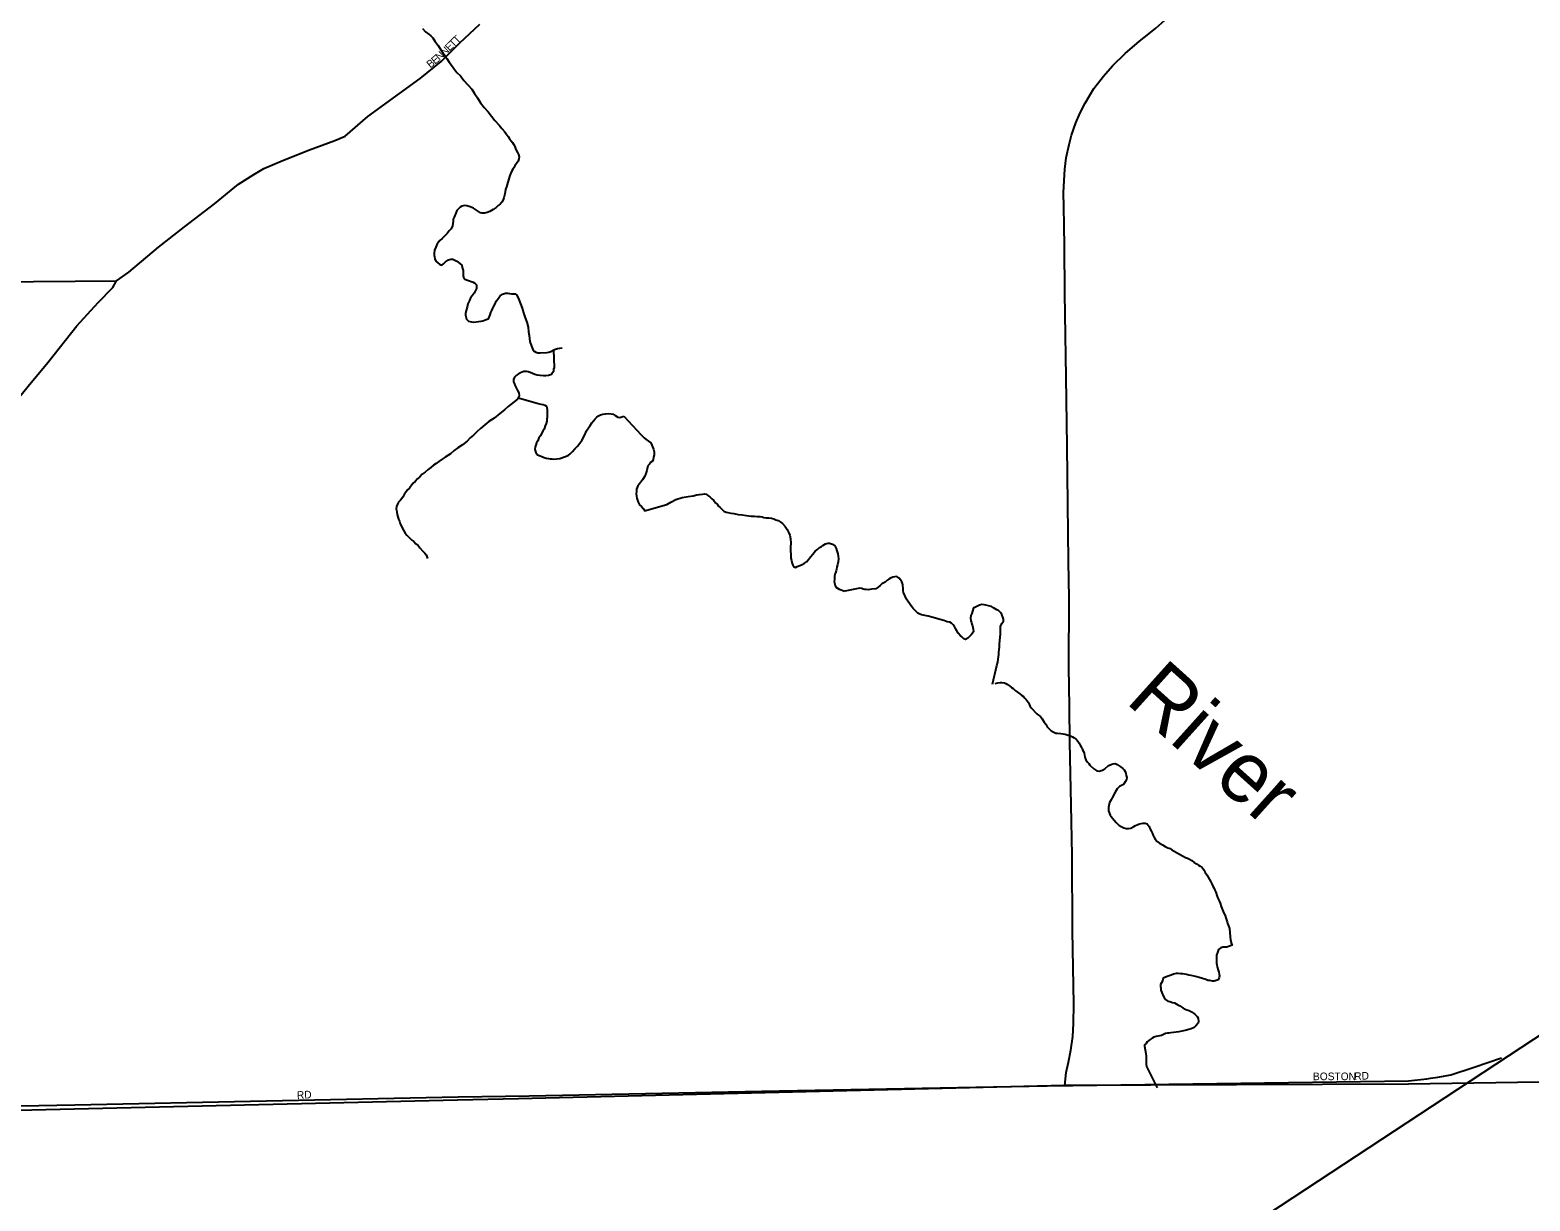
# Model space of a CAD drawing. Extents: x -561 to 1170, y 0 to 846.
# Drawn here: x 187.7 to 214.3, y 67.44 to 88.19 of the extents above; entities that cross this region are included whole.
import ezdxf

# ---------------------------------------------------------------- set-up
doc = ezdxf.new("R2010")
doc.units = 0
for name, color, linetype in [('GM_X_City_Street', 7, 'Continuous'), ('GM_X_City_Street_Text', 7, 'Continuous'), ('GM_X_County', 7, 'Continuous'), ('GM_X_Major_River', 7, 'Continuous'), ('GM_X_Major_River_Text', 7, 'Continuous'), ('GM_X_State_Route', 7, 'Continuous'), ('SH_Text', 7, 'Continuous')]:
    doc.layers.add(name, color=color, linetype=linetype)

msp = doc.modelspace()

# ---------------------------------------------------------------- linework, layer by layer
at = {"layer": 'GM_X_City_Street'}
for points in [[(189.24, 83.747), (189.454, 83.9), (189.985, 84.344), (190.441, 84.705), (190.978, 85.111), (191.401, 85.462), (191.675, 85.632), (191.853, 85.737), (192.202, 85.886), (192.66, 86.069), (193.107, 86.236), (193.29, 86.313), (193.692, 86.664), (194.255, 87.07), (194.62, 87.333), (194.996, 87.634), (195.322, 87.962), (195.681, 88.296)], [(175.794, 83.199), (176.257, 83.284), (177.373, 83.527), (177.605, 83.546), (178.015, 83.593), (178.895, 83.683), (180.439, 83.708), (187.031, 83.731), (189.24, 83.747)], [(179.069, 71.922), (182.409, 75.408), (183.067, 76.215), (184.296, 77.743), (185.113, 78.742), (186.498, 80.439), (187.673, 81.88), (188.021, 82.3), (188.534, 82.949), (188.914, 83.364), (189.176, 83.632), (189.24, 83.747)], [(212.536, 69.612), (212.664, 69.63), (212.897, 69.673), (213.307, 69.809), (213.796, 69.975)], [(178.152, 68.926), (179.747, 68.951), (184.584, 69.065), (186.264, 69.099), (188.502, 69.143), (195.296, 69.284), (196.553, 69.304), (200.677, 69.386), (206.054, 69.485), (206.196, 69.487)], [(206.196, 69.487), (212.144, 69.57), (212.469, 69.603), (212.536, 69.612)]]:
    msp.add_lwpolyline(points, dxfattribs=at)
at = {"layer": 'GM_X_County'}
msp.add_lwpolyline([(282.884, 70.725), (267.704, 70.572), (266.613, 70.549), (250.769, 70.185), (250.464, 70.18), (249.038, 70.146), (242.784, 69.997), (238.571, 69.924), (225.238, 69.779), (224.579, 69.768), (224.275, 69.753), (224.168, 69.735), (224.098, 69.694), (218.724, 69.61), (212.144, 69.507), (206.054, 69.485), (200.736, 69.352), (196.366, 69.25), (195.286, 69.225), (186.974, 69.032)], dxfattribs=at)
at = {"layer": 'GM_X_Major_River'}
for points in [[(194.665, 88.219), (194.714, 88.16), (194.779, 88.117), (194.812, 88.091), (194.845, 88.053), (194.884, 87.994), (194.939, 87.919), (194.989, 87.844), (195.044, 87.763), (195.093, 87.688), (195.138, 87.623), (195.176, 87.57), (195.22, 87.511), (195.27, 87.441), (195.335, 87.382), (195.396, 87.301), (195.467, 87.221), (195.539, 87.146), (195.588, 87.071), (195.638, 86.99), (195.693, 86.904), (195.759, 86.818), (195.825, 86.743), (195.886, 86.668), (195.946, 86.593), (196.023, 86.507), (196.072, 86.448), (196.116, 86.395), (196.149, 86.352), (196.183, 86.309), (196.205, 86.266), (196.238, 86.228), (196.26, 86.201), (196.276, 86.169), (196.298, 86.132), (196.321, 86.078), (196.348, 86.024), (196.365, 85.986), (196.377, 85.948), (196.372, 85.91), (196.361, 85.872), (196.329, 85.829), (196.298, 85.785), (196.282, 85.752), (196.266, 85.725), (196.245, 85.697), (196.224, 85.648), (196.208, 85.6), (196.151, 85.415), (196.135, 85.366), (196.126, 85.29), (196.105, 85.219), (196.094, 85.186), (196.068, 85.143), (196.041, 85.11), (196.004, 85.082), (195.972, 85.049), (195.918, 85.011), (195.859, 84.978), (195.811, 84.961), (195.762, 84.949), (195.724, 84.949), (195.692, 84.954), (195.621, 85.002), (195.566, 85.034), (195.506, 85.06), (195.452, 85.076), (195.414, 85.081), (195.387, 85.08), (195.36, 85.069), (195.333, 85.053), (195.301, 85.025), (195.275, 84.998), (195.254, 84.949), (195.222, 84.878), (195.206, 84.84), (195.207, 84.807)], [(195.207, 84.807), (195.202, 84.764), (195.197, 84.726), (195.171, 84.671), (195.139, 84.633), (195.101, 84.589), (195.059, 84.545), (195.011, 84.501), (194.968, 84.463), (194.925, 84.403), (194.899, 84.348), (194.878, 84.294), (194.868, 84.24), (194.869, 84.202), (194.874, 84.175), (194.88, 84.137), (194.897, 84.099), (194.968, 84.035), (195.006, 84.025), (195.038, 84.052), (195.07, 84.085), (195.124, 84.118), (195.167, 84.13), (195.199, 84.13), (195.227, 84.119), (195.27, 84.098), (195.325, 84.056), (195.358, 84.029), (195.369, 83.986), (195.386, 83.932), (195.387, 83.878), (195.387, 83.84), (195.393, 83.813), (195.415, 83.775), (195.459, 83.759), (195.497, 83.749), (195.524, 83.738), (195.562, 83.723), (195.589, 83.707), (195.622, 83.68), (195.623, 83.61), (195.581, 83.528), (195.543, 83.484), (195.517, 83.446), (195.496, 83.397), (195.469, 83.342), (195.454, 83.283), (195.438, 83.223), (195.428, 83.168), (195.423, 83.141), (195.446, 83.071), (195.479, 83.034), (195.533, 83.023), (195.566, 83.018), (195.706, 83.036), (195.733, 83.042), (195.76, 83.053), (195.808, 83.07), (195.835, 83.076), (195.861, 83.147), (195.877, 83.185), (195.893, 83.223), (195.909, 83.261), (195.924, 83.288), (195.951, 83.343), (195.972, 83.386), (195.998, 83.425), (196.02, 83.457), (196.041, 83.485), (196.084, 83.512), (196.132, 83.529), (196.176, 83.53), (196.208, 83.525), (196.241, 83.52), (196.273, 83.515), (196.306, 83.515), (196.338, 83.494), (196.372, 83.418), (196.4, 83.343), (196.428, 83.262), (196.456, 83.181), (196.484, 83.095), (196.512, 83.014), (196.535, 82.927), (196.541, 82.846), (196.553, 82.781), (196.565, 82.673), (196.593, 82.592), (196.621, 82.533), (196.643, 82.501), (196.671, 82.485), (196.709, 82.474), (196.752, 82.475), (196.865, 82.476), (196.903, 82.482), (196.936, 82.493), (196.978, 82.521), (197.005, 82.532), (197.059, 82.549), (197.097, 82.555), (197.14, 82.561)], [(196.988, 82.525), (196.999, 82.213), (196.988, 82.185), (196.983, 82.142), (196.957, 82.098), (196.93, 82.082), (196.898, 82.07), (196.849, 82.064), (196.806, 82.064), (196.752, 82.069), (196.698, 82.079), (196.654, 82.089), (196.611, 82.105), (196.573, 82.121), (196.535, 82.136), (196.507, 82.142), (196.459, 82.141), (196.432, 82.13), (196.4, 82.119), (196.357, 82.091), (196.324, 82.069), (196.292, 82.041), (196.277, 81.998), (196.277, 81.96), (196.288, 81.933), (196.305, 81.89), (196.327, 81.841), (196.35, 81.804), (196.372, 81.761), (196.378, 81.717), (196.373, 81.685), (196.346, 81.652), (196.234, 81.564), (196.18, 81.52), (196.116, 81.46), (196.036, 81.394), (195.934, 81.311), (195.837, 81.256), (195.768, 81.195), (195.693, 81.129), (195.629, 81.069), (195.57, 81.014), (195.511, 80.965), (195.453, 80.904), (195.372, 80.844), (195.292, 80.789), (195.222, 80.739), (195.158, 80.684), (195.067, 80.623), (195.013, 80.585), (194.954, 80.546), (194.906, 80.513), (194.858, 80.48), (194.809, 80.441), (194.761, 80.403), (194.713, 80.359), (194.66, 80.32), (194.617, 80.276), (194.574, 80.238), (194.532, 80.189), (194.499, 80.161), (194.473, 80.134), (194.43, 80.074), (194.398, 80.041), (194.372, 80.008), (194.345, 79.97), (194.313, 79.915), (194.271, 79.86), (194.239, 79.822), (194.218, 79.789), (194.202, 79.751), (194.197, 79.708), (194.203, 79.681), (194.209, 79.648), (194.215, 79.605), (194.226, 79.567), (194.237, 79.524), (194.254, 79.486), (194.265, 79.443), (194.332, 79.319), (194.354, 79.276), (194.387, 79.239), (194.42, 79.207), (194.447, 79.18), (194.475, 79.153), (194.508, 79.127), (194.546, 79.089), (194.584, 79.057), (194.617, 79.014), (194.672, 78.955), (194.705, 78.923), (194.727, 78.891), (194.738, 78.859), (194.755, 78.826)], [(196.366, 81.676), (196.715, 81.575), (196.764, 81.565), (196.802, 81.555), (196.834, 81.544), (196.862, 81.528), (196.867, 81.501), (196.873, 81.463), (196.874, 81.42), (196.874, 81.377), (196.875, 81.328), (196.87, 81.295), (196.865, 81.263), (196.855, 81.219), (196.839, 81.176), (196.818, 81.121), (196.797, 81.083), (196.776, 81.045), (196.755, 81.001), (196.728, 80.963), (196.707, 80.914), (196.686, 80.876), (196.671, 80.838), (196.66, 80.805), (196.655, 80.756), (196.672, 80.703), (196.705, 80.665), (196.749, 80.644), (196.781, 80.633), (196.819, 80.618), (196.857, 80.607), (196.895, 80.597), (196.928, 80.592), (196.955, 80.592), (196.988, 80.587), (197.047, 80.593), (197.101, 80.599), (197.246, 80.655), (197.284, 80.683), (197.321, 80.721), (197.364, 80.771), (197.412, 80.82), (197.454, 80.869), (197.492, 80.929), (197.539, 81.016), (197.571, 81.087), (197.608, 81.142), (197.634, 81.186), (197.666, 81.229), (197.693, 81.268), (197.725, 81.3), (197.751, 81.328), (197.783, 81.355), (197.821, 81.372), (197.859, 81.383), (197.907, 81.389), (197.967, 81.395), (198.01, 81.391), (198.043, 81.386), (198.081, 81.364), (198.125, 81.332), (198.162, 81.327), (198.233, 81.35)], [(198.233, 81.35), (198.54, 81.018), (198.556, 81.002), (198.595, 80.964), (198.627, 80.938), (198.671, 80.906), (198.709, 80.874), (198.759, 80.766), (198.771, 80.717), (198.772, 80.663), (198.761, 80.62), (198.751, 80.582), (198.741, 80.549), (198.714, 80.532), (198.687, 80.5), (198.661, 80.467), (198.645, 80.418), (198.64, 80.385), (198.624, 80.336), (198.603, 80.287), (198.566, 80.222), (198.508, 80.151), (198.481, 80.112), (198.46, 80.058), (198.455, 80.02), (198.451, 79.971), (198.457, 79.933), (198.462, 79.896), (198.474, 79.858), (198.485, 79.825), (198.513, 79.777), (198.546, 79.75), (198.579, 79.707), (198.606, 79.664)], [(198.601, 79.672), (198.994, 79.783), (199.064, 79.822), (199.155, 79.871), (199.268, 79.905), (199.371, 79.923), (199.463, 79.94), (199.527, 79.952), (199.576, 79.963), (199.63, 79.969), (199.662, 79.97), (199.69, 79.965), (199.722, 79.943), (199.76, 79.917), (199.793, 79.885), (199.826, 79.853), (199.859, 79.815), (199.892, 79.783), (199.914, 79.756), (199.941, 79.729), (199.974, 79.692), (200.007, 79.665), (200.045, 79.649), (200.078, 79.639), (200.127, 79.629), (200.186, 79.624), (200.262, 79.609), (200.333, 79.599), (200.408, 79.589), (200.49, 79.579), (200.549, 79.574), (200.598, 79.57), (200.652, 79.57), (200.685, 79.565), (200.717, 79.555), (200.755, 79.55), (200.804, 79.545), (200.853, 79.54), (200.891, 79.53), (200.929, 79.514), (200.967, 79.498), (201.005, 79.477), (201.043, 79.445), (201.093, 79.391), (201.126, 79.343), (201.153, 79.295), (201.176, 79.241), (201.187, 79.176), (201.194, 79.105), (201.189, 79.03), (201.192, 78.835), (201.203, 78.791), (201.215, 78.737), (201.231, 78.71), (201.242, 78.684), (201.275, 78.668), (201.307, 78.684), (201.356, 78.701), (201.393, 78.718), (201.436, 78.745), (201.469, 78.768), (201.506, 78.811), (201.543, 78.855), (201.586, 78.904), (201.628, 78.954), (201.671, 78.992), (201.703, 79.02), (201.73, 79.036), (201.762, 79.058), (201.811, 79.086), (201.848, 79.097), (201.881, 79.098), (201.935, 79.082), (201.973, 79.05), (201.996, 79.001), (202.007, 78.964), (202.024, 78.91), (202.035, 78.867), (202.036, 78.818), (202.031, 78.769), (202.021, 78.715), (202.011, 78.671), (202.006, 78.639), (201.995, 78.606), (201.985, 78.573), (201.974, 78.546), (201.97, 78.508), (201.965, 78.454), (201.96, 78.416), (201.977, 78.346), (201.994, 78.319), (202.048, 78.282), (202.153, 78.245)], [(204.771, 76.598), (204.847, 76.931), (204.862, 76.991), (204.871, 77.04), (204.876, 77.083), (204.88, 77.127), (204.884, 77.165), (204.888, 77.214), (204.892, 77.257), (204.896, 77.312), (204.9, 77.366), (204.904, 77.431), (204.908, 77.485), (204.913, 77.513), (204.912, 77.551), (204.91, 77.621), (204.935, 77.676), (204.967, 77.715), (204.966, 77.753), (204.954, 77.785), (204.936, 77.833), (204.908, 77.87), (204.875, 77.902), (204.848, 77.917), (204.787, 77.954), (204.749, 77.975), (204.699, 77.99), (204.65, 77.999), (204.623, 78.004), (204.58, 78.008), (204.537, 78.002), (204.489, 77.973), (204.457, 77.956), (204.43, 77.95), (204.415, 77.89), (204.4, 77.852), (204.385, 77.813), (204.38, 77.775), (204.387, 77.721), (204.399, 77.689), (204.405, 77.662), (204.417, 77.63), (204.423, 77.603), (204.429, 77.576), (204.43, 77.527), (204.389, 77.472), (204.331, 77.416), (204.288, 77.393), (204.26, 77.403), (204.227, 77.435), (204.2, 77.456), (204.16, 77.504), (204.138, 77.546), (204.121, 77.573), (204.098, 77.621), (204.07, 77.653), (204.042, 77.679), (204.014, 77.695), (203.965, 77.705), (203.905, 77.725), (203.818, 77.749), (203.72, 77.779), (203.627, 77.804), (203.54, 77.823), (203.513, 77.828), (203.48, 77.838), (203.447, 77.859), (203.403, 77.896), (203.364, 77.938), (203.347, 77.965), (203.319, 77.991), (203.296, 78.029), (203.268, 78.071), (203.245, 78.108), (203.193, 78.221), (203.187, 78.259), (203.186, 78.297), (203.179, 78.351), (203.173, 78.383), (203.161, 78.41), (203.139, 78.447), (203.116, 78.479), (203.072, 78.505), (203.04, 78.504), (203.002, 78.498), (202.959, 78.48), (202.933, 78.458), (202.895, 78.435), (202.864, 78.407), (202.832, 78.39), (202.805, 78.379), (202.779, 78.346), (202.741, 78.318), (202.699, 78.289), (202.629, 78.282), (202.596, 78.276), (202.564, 78.27), (202.531, 78.274), (202.504, 78.279), (202.477, 78.283), (202.45, 78.294)], [(202.45, 78.294), (202.417, 78.298), (202.153, 78.245)], [(204.818, 76.61), (204.861, 76.622), (204.909, 76.629), (204.936, 76.63), (204.98, 76.62), (205.007, 76.61), (205.035, 76.594), (205.073, 76.568), (205.107, 76.542), (205.134, 76.521), (205.173, 76.489), (205.212, 76.458), (205.251, 76.426), (205.289, 76.4), (205.317, 76.379), (205.345, 76.353), (205.367, 76.326), (205.401, 76.279), (205.418, 76.246), (205.43, 76.214), (205.452, 76.182), (205.553, 76.071), (205.586, 76.05), (205.619, 76.024)], [(205.619, 76.024), (205.647, 75.987), (205.669, 75.955), (205.686, 75.928), (205.714, 75.891), (205.737, 75.843), (205.76, 75.816), (205.81, 75.774), (205.843, 75.753), (205.892, 75.733), (205.924, 75.728), (205.979, 75.724), (206.022, 75.72), (206.06, 75.71), (206.109, 75.695), (206.153, 75.68), (206.186, 75.665), (206.219, 75.649), (206.252, 75.623), (206.28, 75.591), (206.303, 75.554), (206.325, 75.517), (206.342, 75.49), (206.359, 75.463), (206.365, 75.436), (206.383, 75.404), (206.394, 75.378), (206.401, 75.34), (206.407, 75.302), (206.424, 75.259), (206.453, 75.216), (206.475, 75.19), (206.497, 75.163), (206.564, 75.1), (206.619, 75.064), (206.663, 75.059), (206.695, 75.066), (206.722, 75.072), (206.759, 75.1), (206.828, 75.156), (206.903, 75.185), (206.941, 75.191), (206.979, 75.176), (207.034, 75.14), (207.078, 75.103), (207.106, 75.082), (207.123, 75.05), (207.135, 75.018), (207.141, 74.98), (207.148, 74.947), (207.143, 74.909), (207.123, 74.865), (207.091, 74.821), (207.054, 74.804), (207.022, 74.787), (206.98, 74.742), (206.943, 74.687), (206.892, 74.583), (206.871, 74.55), (206.846, 74.5), (206.835, 74.473), (206.831, 74.44), (206.826, 74.413), (206.827, 74.386), (206.828, 74.353), (206.857, 74.278), (206.874, 74.252), (206.896, 74.225), (206.924, 74.188), (206.963, 74.146), (207.008, 74.098), (207.052, 74.077), (207.096, 74.051), (207.139, 74.042), (207.183, 74.043), (207.22, 74.049), (207.274, 74.078), (207.306, 74.095), (207.333, 74.107), (207.359, 74.118), (207.402, 74.13), (207.44, 74.136), (207.478, 74.132), (207.511, 74.122), (207.545, 74.074), (207.567, 74.031), (207.59, 73.989), (207.602, 73.962), (207.619, 73.919), (207.631, 73.892), (207.654, 73.849), (207.687, 73.812), (207.731, 73.781), (207.781, 73.75), (207.83, 73.724), (207.88, 73.698), (207.918, 73.683), (207.951, 73.662), (207.989, 73.641), (208.033, 73.615), (208.193, 73.527)], [(208.193, 73.527), (208.226, 73.512), (208.259, 73.497), (208.303, 73.471), (208.347, 73.439), (208.385, 73.413), (208.424, 73.392), (208.452, 73.372), (208.485, 73.351), (208.518, 73.308), (208.541, 73.26), (208.569, 73.217), (208.592, 73.175), (208.615, 73.137), (208.638, 73.094), (208.655, 73.057), (208.678, 73.02), (208.695, 72.988), (208.712, 72.95), (208.729, 72.913), (208.747, 72.853), (208.765, 72.805), (208.788, 72.757), (208.805, 72.714), (208.823, 72.655), (208.846, 72.596), (208.869, 72.537), (208.892, 72.499), (208.904, 72.456), (208.916, 72.419), (208.927, 72.386), (208.934, 72.354), (208.951, 72.317), (208.969, 72.268), (208.976, 72.193), (208.99, 72.063), (209.008, 71.998), (209.02, 71.971), (208.923, 71.936), (208.891, 71.936), (208.853, 71.935), (208.815, 71.923), (208.778, 71.895), (208.758, 71.84), (208.743, 71.796), (208.739, 71.742), (208.74, 71.693), (208.741, 71.655), (208.748, 71.623), (208.754, 71.59), (208.772, 71.531), (208.784, 71.494), (208.785, 71.456), (208.791, 71.429), (208.786, 71.396), (208.771, 71.358), (208.701, 71.334), (208.669, 71.333), (208.625, 71.343), (208.587, 71.347), (208.549, 71.363), (208.494, 71.383), (208.434, 71.398), (208.391, 71.413), (208.342, 71.422), (208.293, 71.432), (208.249, 71.442), (208.211, 71.451), (208.146, 71.461), (208.102, 71.465), (208.059, 71.469), (208.026, 71.468), (207.978, 71.456), (207.935, 71.439), (207.882, 71.421), (207.839, 71.404), (207.796, 71.386), (207.781, 71.332), (207.766, 71.304), (207.75, 71.277), (207.746, 71.239), (207.752, 71.212), (207.753, 71.174), (207.77, 71.136), (207.788, 71.088), (207.81, 71.045), (207.839, 71.008), (207.877, 70.982), (207.915, 70.972), (207.959, 70.957), (207.997, 70.947), (208.025, 70.931), (208.052, 70.916), (208.091, 70.895), (208.146, 70.864), (208.184, 70.838), (208.217, 70.828), (208.255, 70.813), (208.299, 70.792), (208.332, 70.766), (208.365, 70.745)], [(208.365, 70.745), (208.399, 70.708), (208.416, 70.676), (208.423, 70.617), (208.413, 70.589), (208.376, 70.54), (208.345, 70.512), (208.291, 70.488), (208.248, 70.477), (208.184, 70.459), (208.124, 70.446), (208.071, 70.434), (207.93, 70.419), (207.898, 70.413), (207.871, 70.412), (207.839, 70.406), (207.764, 70.372), (207.672, 70.353), (207.629, 70.341), (207.597, 70.324), (207.565, 70.301), (207.539, 70.284), (207.512, 70.257), (207.491, 70.229), (207.465, 70.207), (207.466, 70.179), (207.478, 70.115), (207.485, 70.05), (207.492, 70.001), (207.494, 69.942), (207.495, 69.893), (207.496, 69.86), (207.502, 69.823), (207.691, 69.446)]]:
    msp.add_lwpolyline(points, dxfattribs=at)
at = {"layer": 'GM_X_State_Route'}
for points in [[(207.541, 88.128), (207.662, 88.226), (207.875, 88.414), (208.089, 88.644), (208.3, 88.889), (208.851, 89.571), (209.201, 90.085)], [(206.034, 85.067), (206.029, 85.309), (206.037, 85.528), (206.049, 85.727), (206.078, 85.931), (206.13, 86.167), (206.171, 86.333), (206.244, 86.549), (206.326, 86.728), (206.409, 86.897), (206.568, 87.155), (206.738, 87.377), (206.896, 87.56), (207.123, 87.777), (207.377, 87.995), (207.541, 88.128)], [(206.118, 78.772), (206.094, 80.815), (206.078, 82.043), (206.049, 83.531), (206.045, 84.361), (206.041, 84.723), (206.034, 85.067)], [(206.054, 69.485), (206.077, 69.714), (206.118, 69.898), (206.16, 70.109), (206.192, 70.356), (206.205, 70.585), (206.21, 70.924), (206.185, 72.228), (206.182, 73.563), (206.166, 74.458), (206.143, 75.573), (206.137, 76.202), (206.122, 76.899), (206.126, 78.122), (206.118, 78.772)]]:
    msp.add_lwpolyline(points, dxfattribs=at)
at = {"layer": 'SH_Text'}
msp.add_lwpolyline([(203.796, 63.354), (276.905, 111.448), (203.796, 42.031)], close=True, dxfattribs=at)

# ---------------------------------------------------------------- texts
at = {"layer": 'GM_X_City_Street_Text'}
for s, rotation, p in [('T', 44.0959, (195.21, 87.877)), ('T', 44.0959, (195.278, 87.943)), ('N', 42.7305, (194.966, 87.645)), ('N', 44.0499, (195.056, 87.728)), ('E', 44.0781, (195.141, 87.811)), ('B', 38.7546, (194.802, 87.512)), ('E', 39.2481, (194.886, 87.579)), ('BOSTON', 0, (210.451, 69.579)), ('RD', 3.011, (211.186, 69.579)), ('RD', 3.011, (192.44, 69.246))]:
    msp.add_text(s, height=0.135, rotation=rotation, dxfattribs=at).set_placement(p)
at = {"layer": 'GM_X_Major_River_Text'}
msp.add_text('River', height=1.0806, rotation=318.0221, dxfattribs=at).set_placement((207.108, 76.286))

doc.saveas('drawing.dxf')
